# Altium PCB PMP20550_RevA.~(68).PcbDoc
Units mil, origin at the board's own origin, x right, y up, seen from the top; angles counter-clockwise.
Board outline 1966.66 x 1968.77 mil, 4 copper layers (Top Layer, POWER, GNDS, Bottom Layer), stack 79.834 mil thick; 56 components, 23 nets, 129 pads, 56 vias.
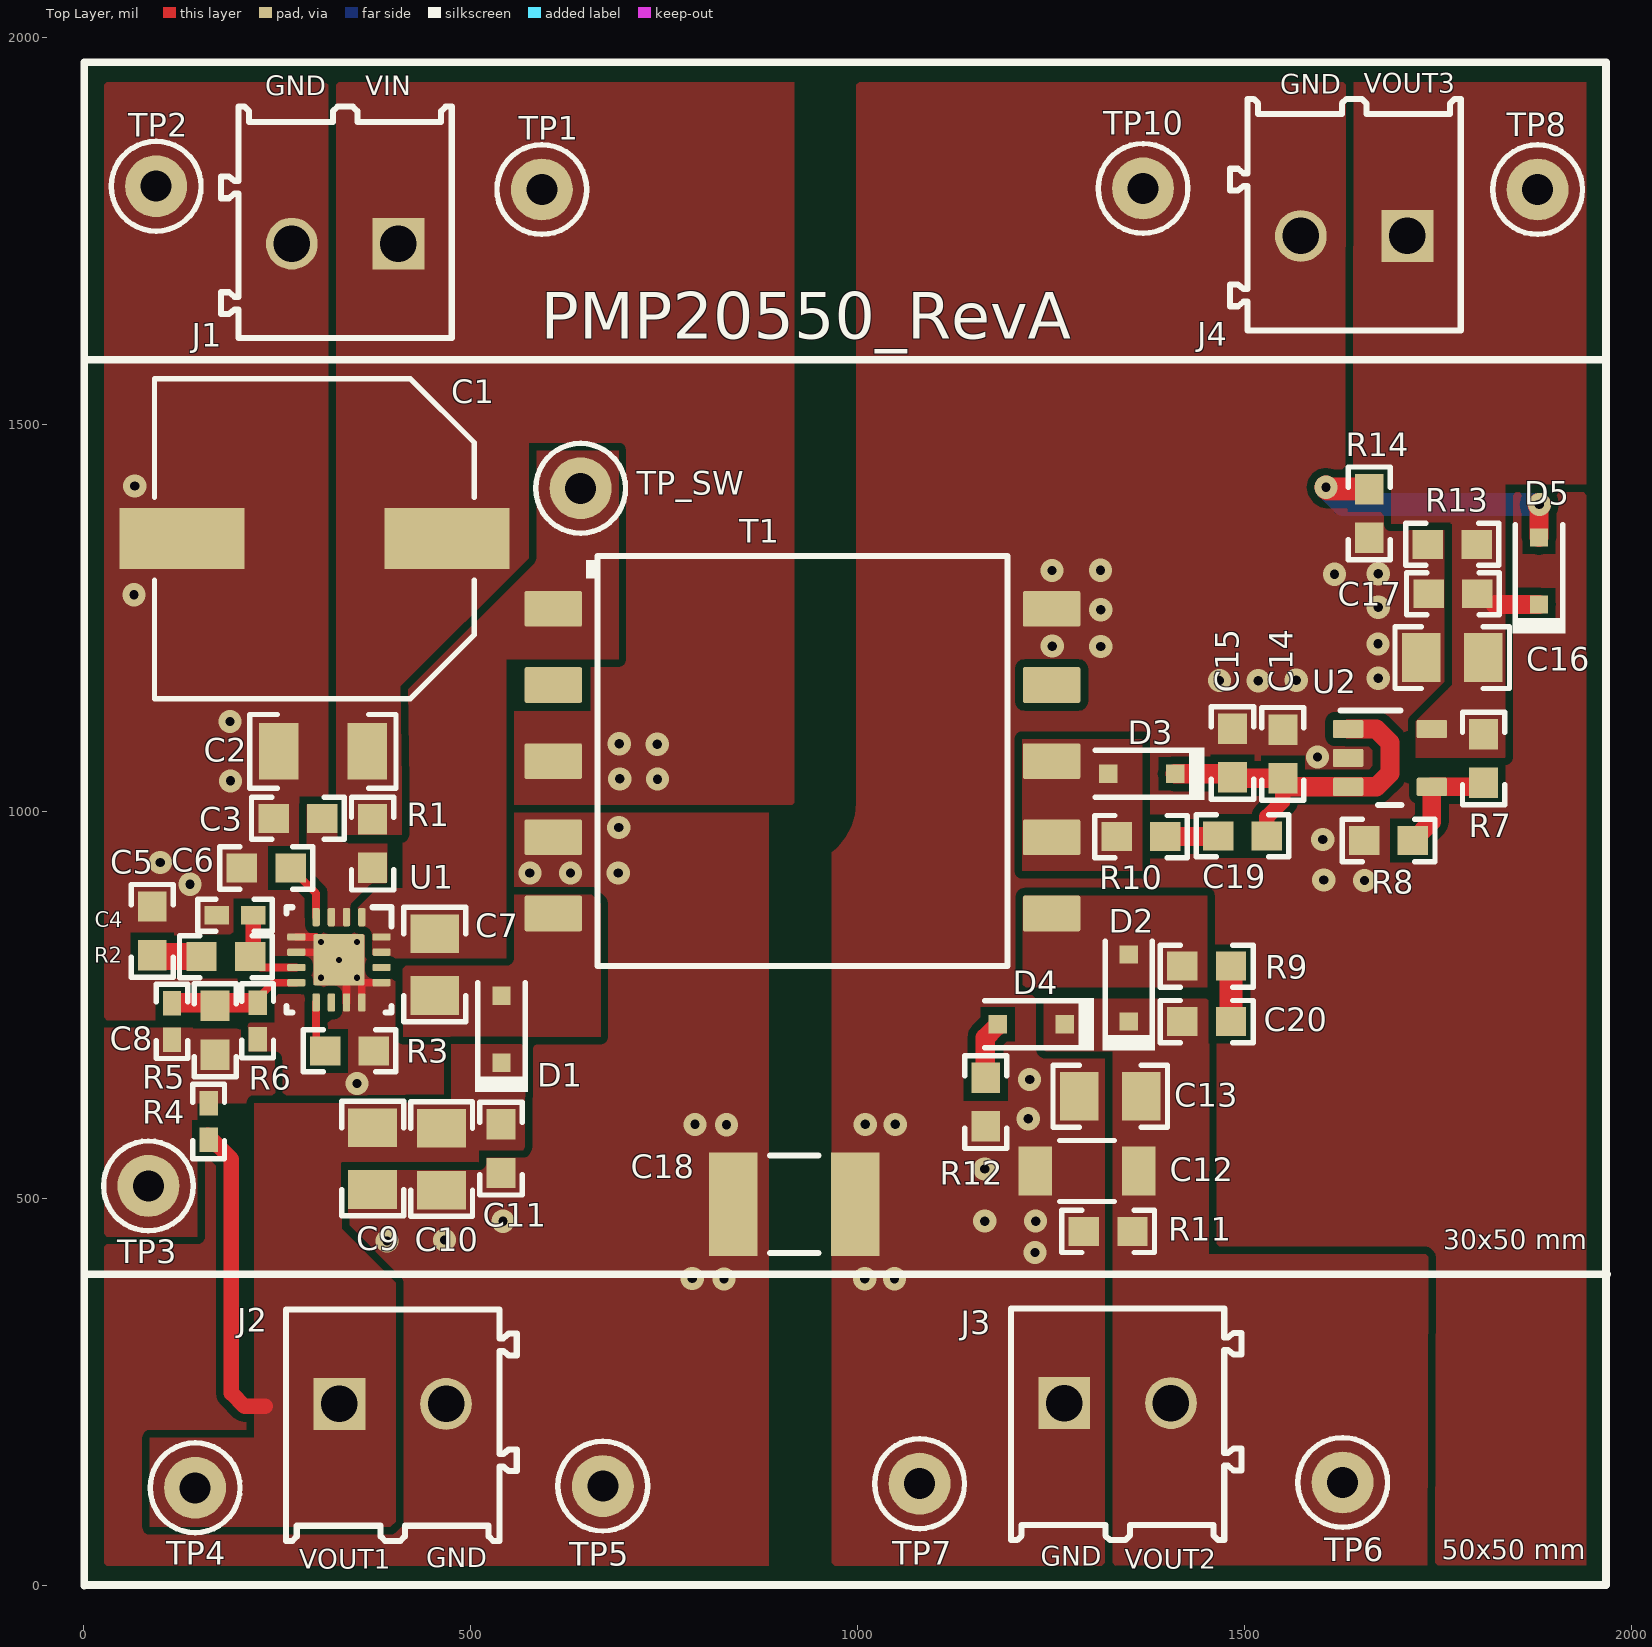
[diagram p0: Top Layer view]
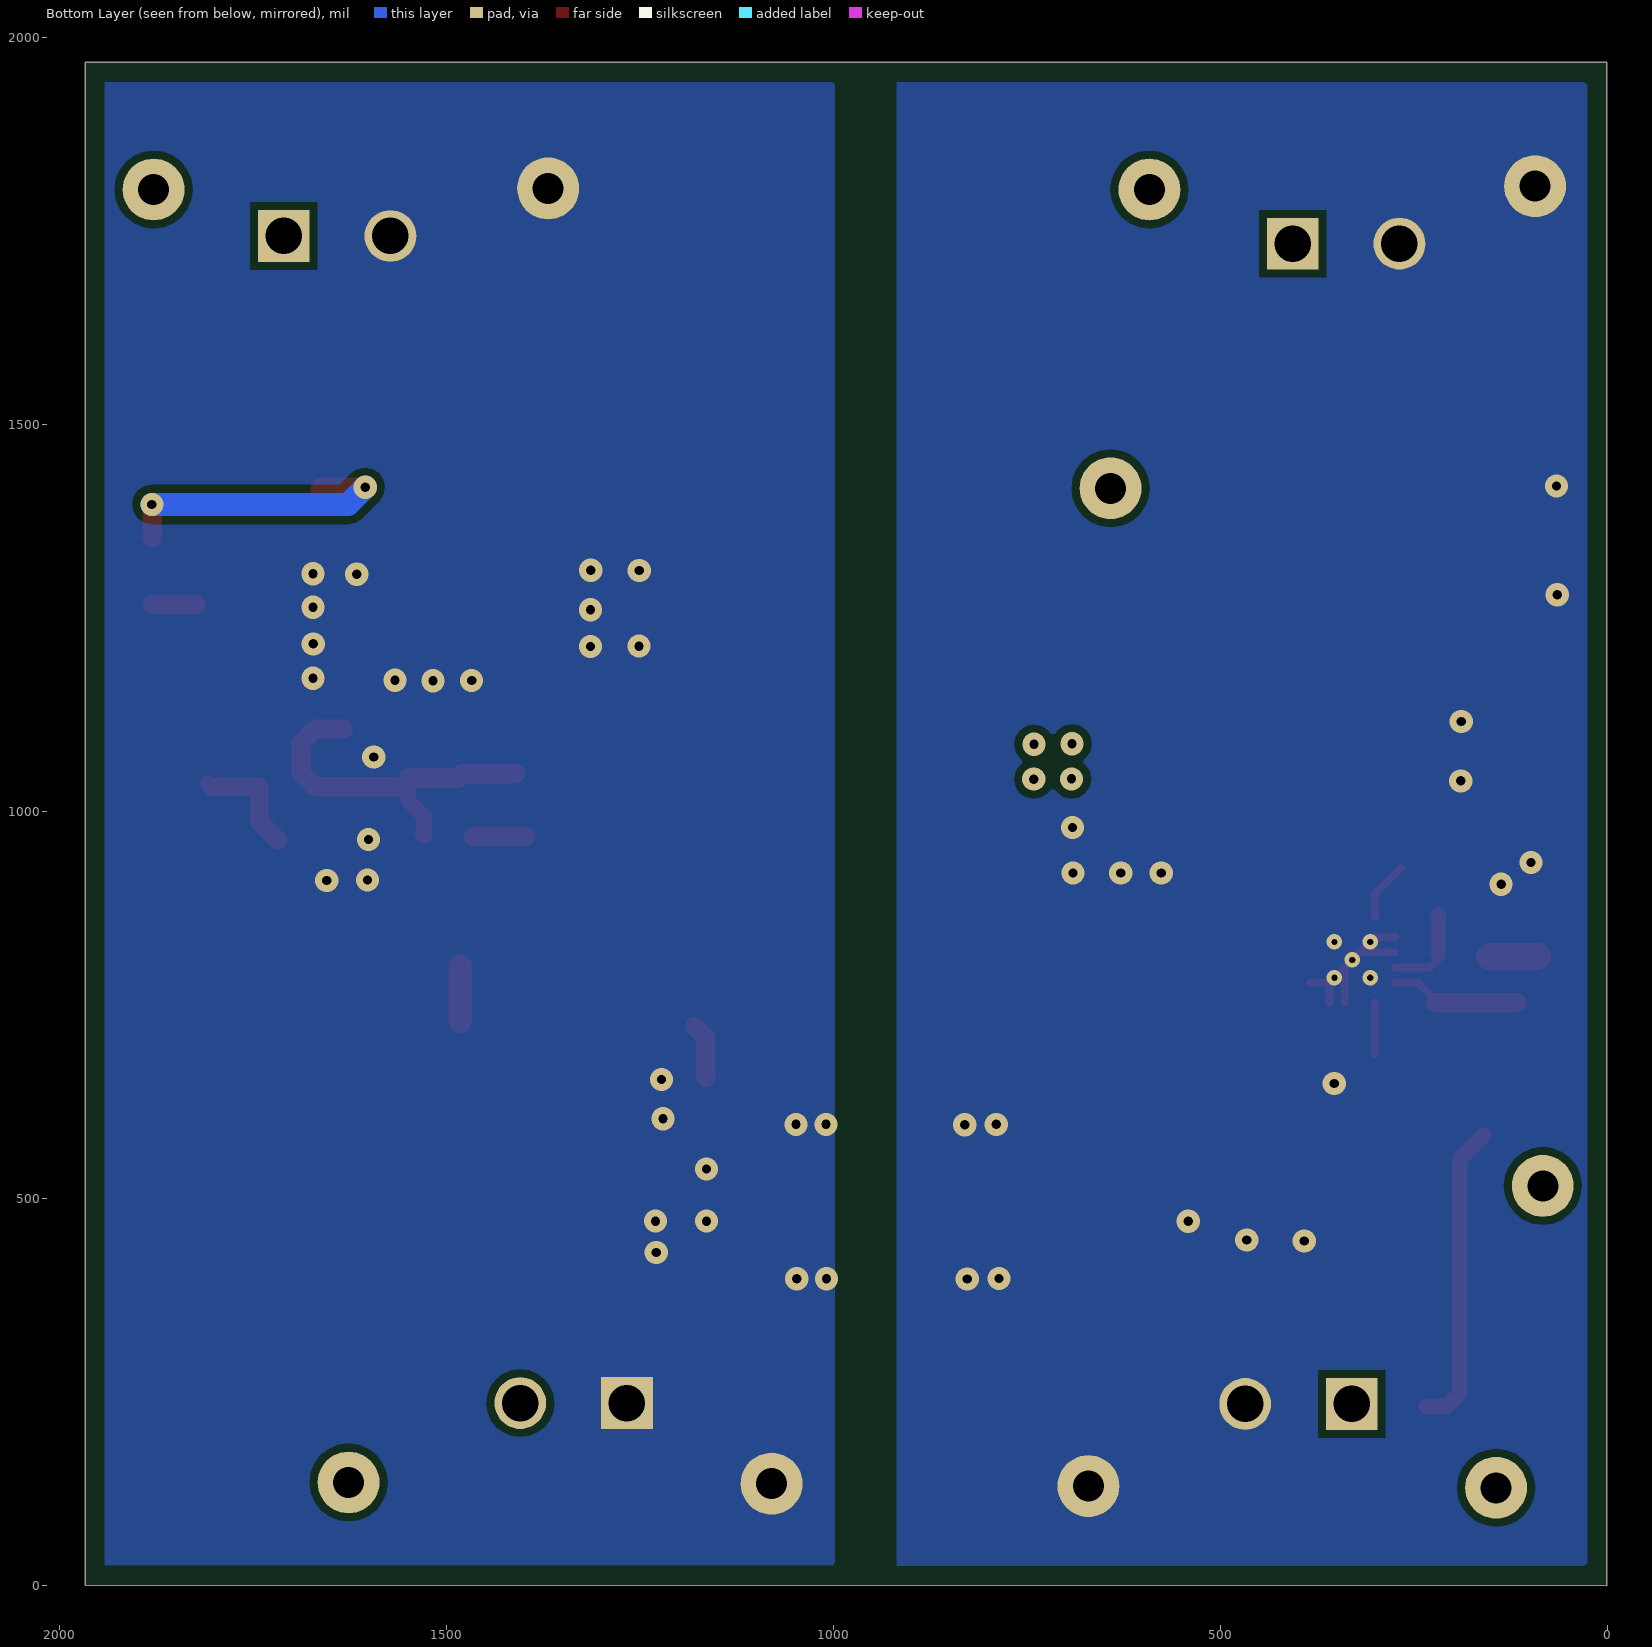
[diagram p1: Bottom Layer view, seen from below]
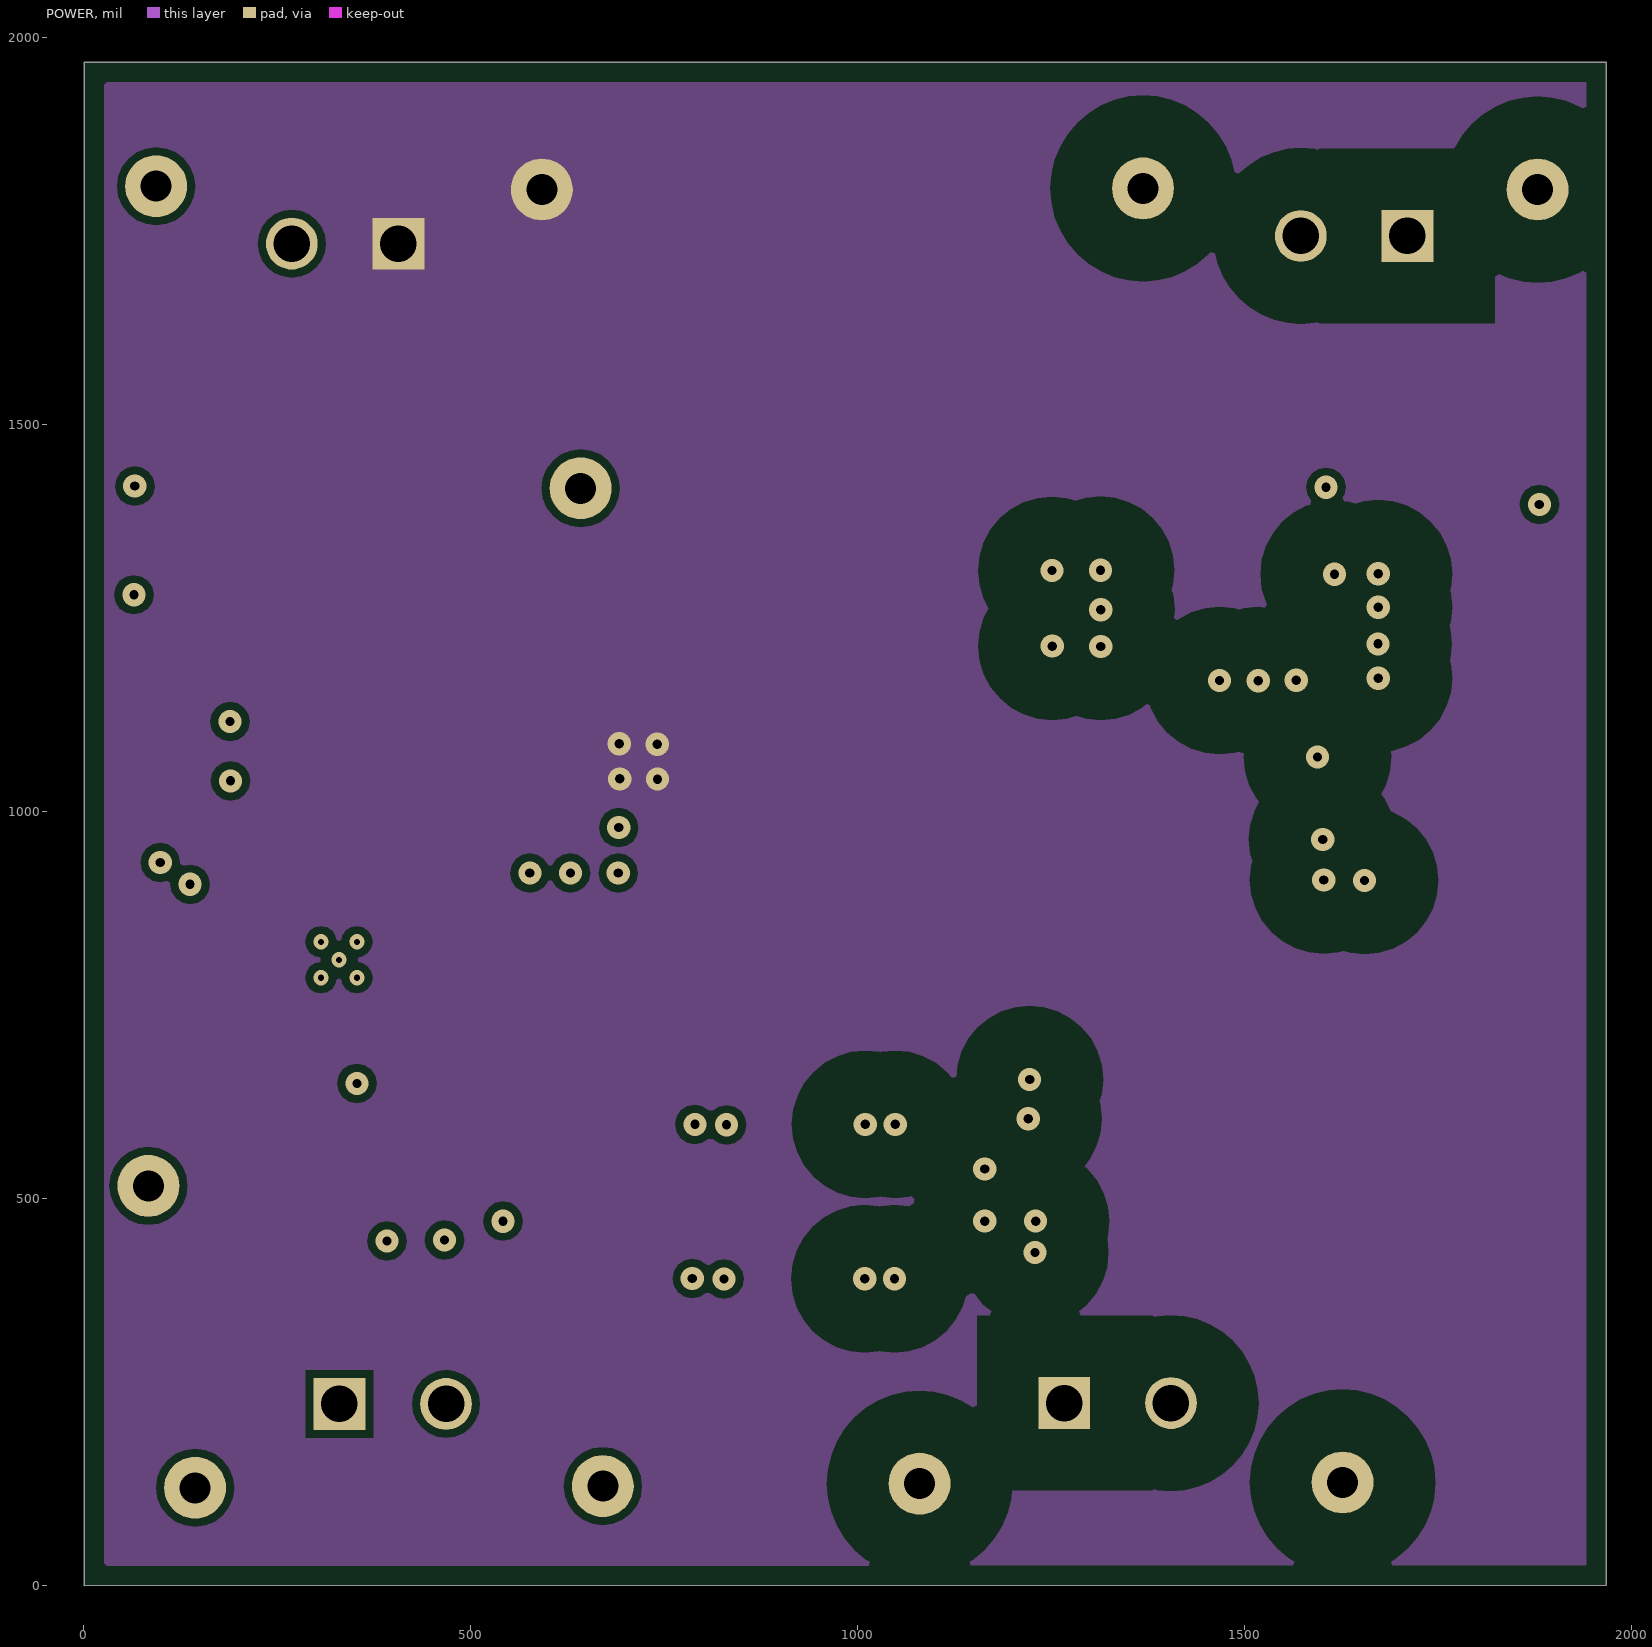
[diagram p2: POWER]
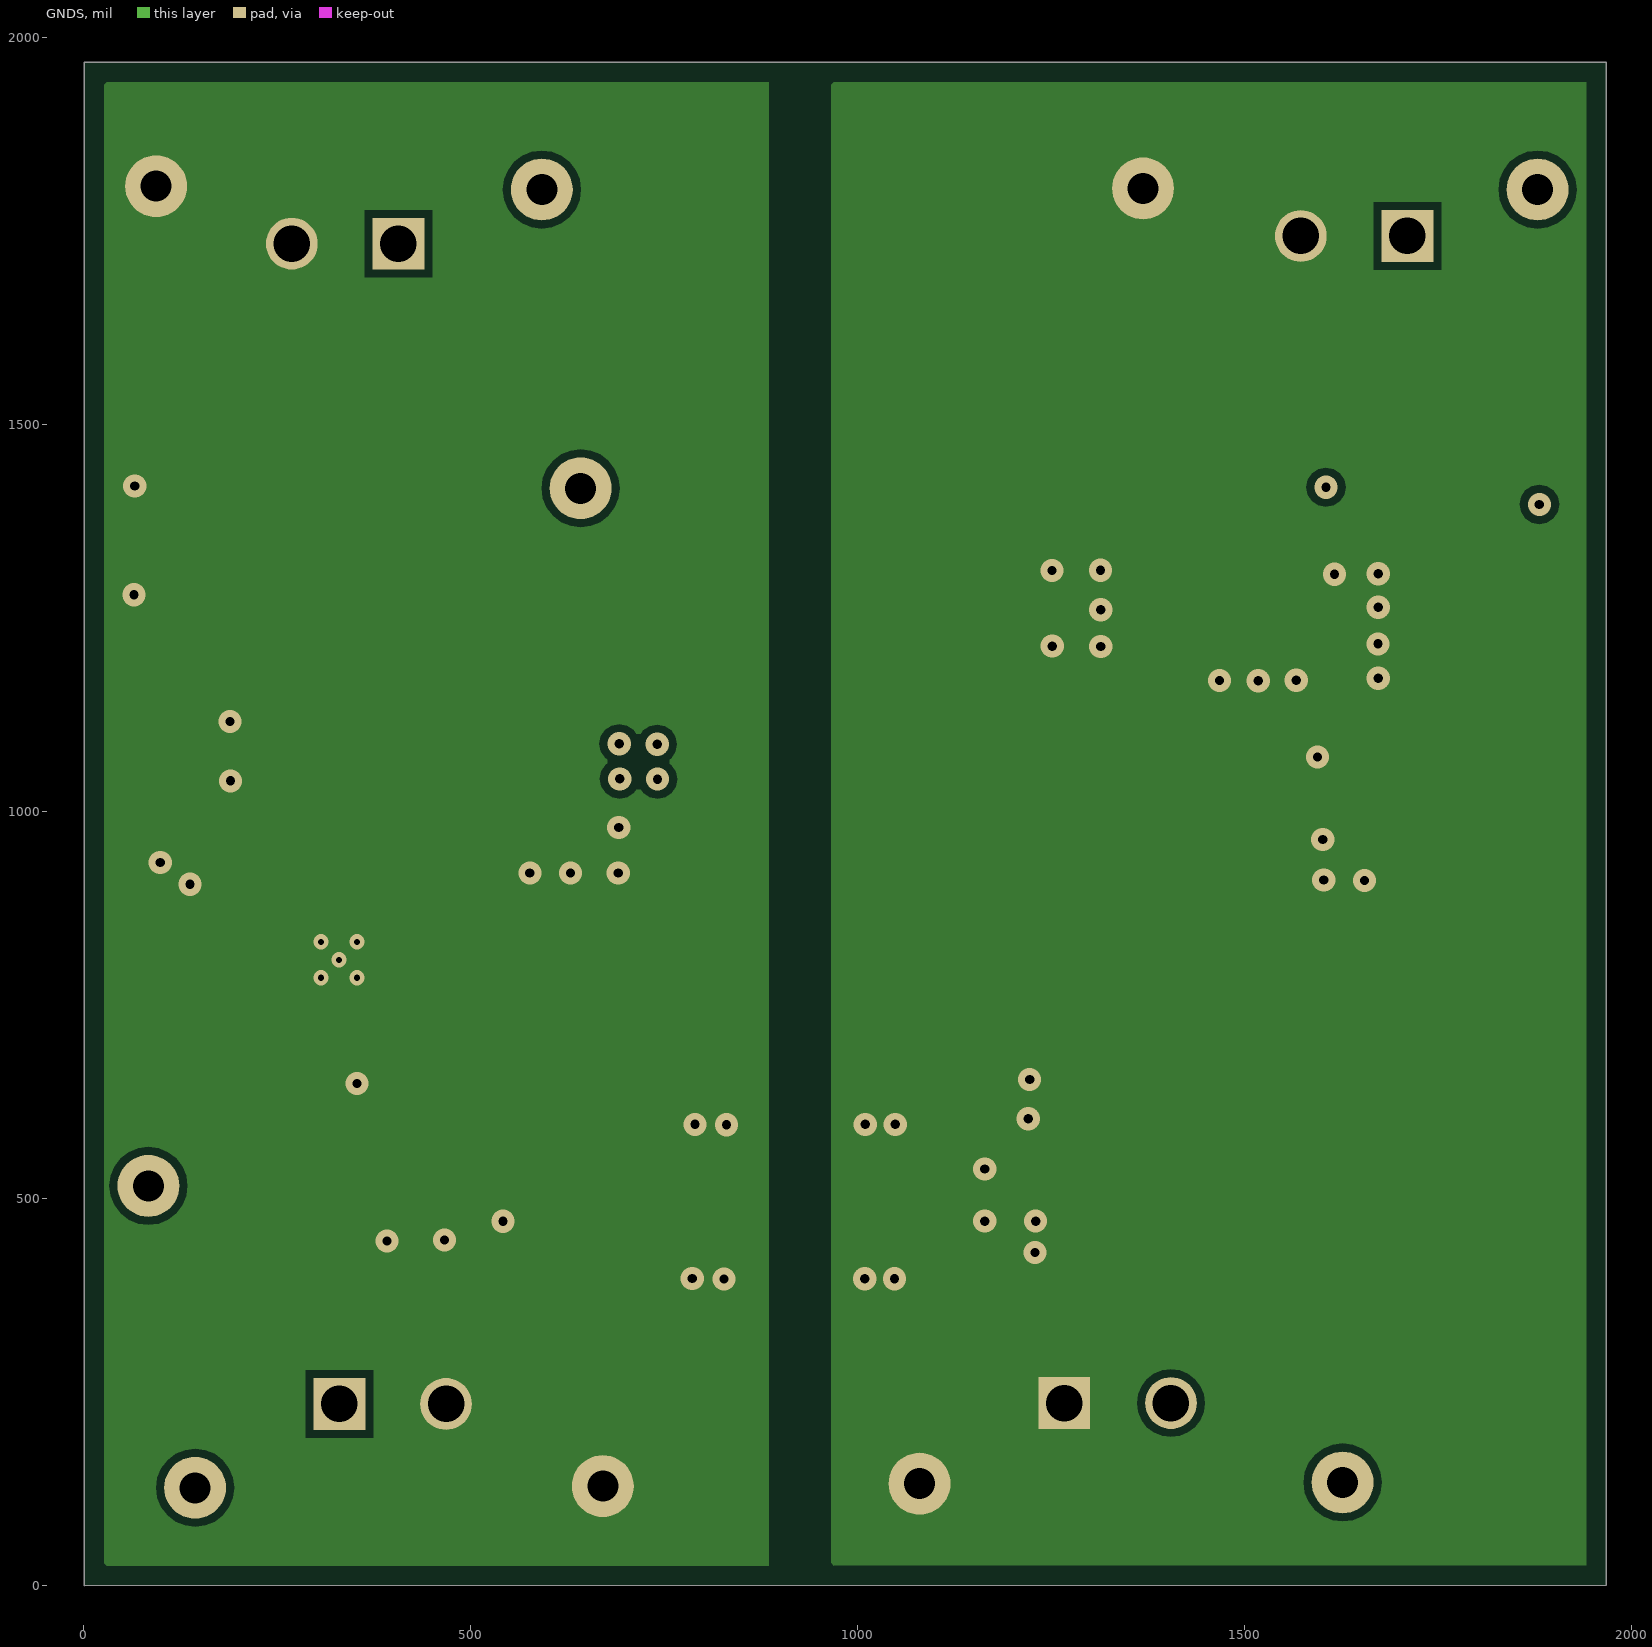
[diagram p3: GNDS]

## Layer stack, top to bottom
Top Solder: solder mask 0.4, Solder Resist, Dk 3.5
Top Layer: signal copper 1.4
Dielectric1: core 59.2, FR-4, Dk 4.8
POWER: signal copper 1.417
Dielectric 3: prepreg 5, Dk 4.2
GNDS: signal copper 1.417
Dielectric 2: core 10, Dk 4.2
Bottom Layer: signal copper 1.4
Bottom Solder: solder mask 0.4, Solder Resist, Dk 3.5

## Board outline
0.76,-0.43 0.76,1968.34 0.81,1968.29 1967.33,1968.29 1967.42,1968.2 1967.42,0.32 1967.36,0.38

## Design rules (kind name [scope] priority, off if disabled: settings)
AcuteAngle [All] p1: minimum=4.50000000000000E+0001 checktracksonly=FALSE
AssemblyTestPointUsage [All] p1: valid=2
BoardOutlineClearance BoardOutlineClearance_MountingHoles [OnCopper and InComponentClass('Mounting Holes')] p1: gap=40
BoardOutlineClearance BoardOutlineClearance_Poly [OnCopper and IsPoly] p2: gap=25
BoardOutlineClearance [OnCopper and Not InComponentClass('Logo') and not InComponentClass('FiducialMark') and not InRegion(1000,500,4000,800) and not InPoly] p3: gap=40
Clearance Clearance_2 [InNet('NetC1_1') vs InNetClass('Undefined')] p1: gap=80
Clearance Clearance_1 [InNet('GND') vs InNet('GND2')] p2: gap=80
Clearance Clearance_Keepouts [((IsTrack Or IsArc) And Not InPoly) And IsFree and IsKeepOut vs ((IsTrack Or IsArc) And Not InPoly) And IsFree and IsKeepOut] p3: gap=0
Clearance Clearance_Poly [InPolygon] p4: gap=10
Clearance [All] p5: gap=5
ComponentClearance ComponentClearance_MountingHoles_FiducialMarks [InComponentClass('Mounting Holes') vs InComponentClass('FiducialMark')] p1: gap=50 collisioncheckmode=3 verticalgap=10 showdistances=FALSE
ComponentClearance ComponentClearance_Shunt [InComponentClass('Header') vs InComponentClass('Shunt')] p2: gap=0 collisioncheckmode=3 verticalgap=0 showdistances=FALSE
ComponentClearance ComponentClearance_Logo [InComponentClass('Logo')] p3: gap=50 collisioncheckmode=3 verticalgap=10 showdistances=FALSE
ComponentClearance ComponentClearance_ScrewToNut [(HasFootprint('NY PMS 440 0025 PH')) vs (HasFootprint('Keystone_1902C'))] p4: gap=5 collisioncheckmode=3 verticalgap=10 showdistances=FALSE
ComponentClearance ComponentClearance_MountingHoles [InComponentClass('Mounting Holes')] p5: gap=250 collisioncheckmode=3 verticalgap=100000 showdistances=FALSE
ComponentClearance ComponentClearance_SmallPassives [HasFootprint('0201*') or HasFootprint('0402*') or HasFootprint('0508') or HasFootprint('0603*') or HasFootprint('0612') or HasFootprint('0805*') or HasFootprint('0815*') or HasFootprint('0830*') or HasFootprint('1206*') or HasFootprint('1210*') or HasFootprint('1808*') or HasFootprint('1812*') or HasFootprint('1825*') or HasFootprint('2010*') or HasFootprint('2220*') or HasFootprint('2225*') or HasFootprint('2512*') or HasFootprint('2728*') or HasFootprint('3518*') vs HasFootprint('0201*') or HasFootprint('0402*') or HasFootprint('0508') or HasFootprint('0603*') or HasFootprint('0612') or HasFootprint('0805*') or HasFootprint('0815*') or HasFootprint('0830*') or HasFootprint('1206*') or HasFootprint('1210*') or HasFootprint('1808*') or HasFootprint('1812*') or HasFootprint('1825*') or HasFootprint('2010*') or HasFootprint('2220*') or HasFootprint('2225*') or HasFootprint('2512*') or HasFootprint('2728*') or HasFootprint('3518*')] p6: gap=14.96 collisioncheckmode=3 verticalgap=10 showdistances=FALSE
ComponentClearance ComponentClearance_THtoSMT [IsThruComponent vs IsSMTComponent] p7: gap=40 collisioncheckmode=3 verticalgap=30 showdistances=FALSE
ComponentClearance ComponentClearance_THtoTH [IsThruComponent vs IsThruComponent] p8: gap=30 collisioncheckmode=3 verticalgap=30 showdistances=FALSE
ComponentClearance [All] p9: gap=30 collisioncheckmode=3 verticalgap=10 showdistances=FALSE
DiffPairsRouting [All] p1: maxlimit=100 minlimit=10 mostfreqgap=10 toplayer_minwidth=15 toplayer_maxwidth=15 toplayer_prefwidth=15 midlayer1_minwidth=15 midlayer1_maxwidth=15 midlayer1_prefwidth=15 midlayer2_minwidth=15 midlayer2_maxwidth=15 midlayer2_prefwidth=15 bottomlayer_minwidth=15 bottomlayer_maxwidth=15 bottomlayer_prefwidth=15 maxuncoupledlength=1000
FabricationTestPointUsage TestPointUsage [All] p1: valid=2 allowmultiple=FALSE
FabricationTestpoint Testpoint [All] p1: side=3 testpointundercomponent=TRUE minsize=40 maxsize=100 preferedsize=60 minholesize=0 maxholesize=40 preferedholesize=32 testpointgrid=1 allowsidetop=TRUE allowsidebottom=TRUE usegrid=TRUE gridtolerance=0.01
FanoutControl Fanout_LCC [IsLCC] p1: bgadir=Out bgaviamode=Centered fanoutstyle=Auto fanoutdirection=Alternating viagrid=1 // Fanout_LCC (Default Rule)
FanoutControl Fanout_BGA [IsBGA] p2: bgadir=Out bgaviamode=Centered fanoutstyle=Auto fanoutdirection=Alternating viagrid=1 // Fanout_BGA (Default Rule)
FanoutControl Fanout_Default [All] p4: bgadir=Out bgaviamode=Centered fanoutstyle=Auto fanoutdirection=Alternating viagrid=1 // Fanout_Default (Default Rule)
FanoutControl Fanout_Small [(CompPinCount < 5)] p5: bgadir=Out bgaviamode=Centered fanoutstyle=Auto fanoutdirection=OutThenIn viagrid=1 // Fanout_Small (Default Rule)
HoleSize [All] p1: absolutevalues=TRUE maxlimit=251 minlimit=7.87 maxpercent=80.000 minpercent=20.000
MinimumAnnularRing MinimumAnnularRing_ThermalPadVias [IsVia and InAnyComponent] p1: minimumring=5.91
MinimumAnnularRing [All] p2: minimumring=8
MinimumSolderMaskSliver MinimumSolderMaskSliver_Logo [InComponentClass('Logo') vs InComponentClass('Logo')] p1: minsoldermaskwidth=0.7
MinimumSolderMaskSliver [All] p2: minsoldermaskwidth=3.94
PlaneConnect [All] p1: planeconnectstyle=Direct reliefexpansion=10 reliefentries=4 reliefconductorwidth=10 reliefairgap=10
PolygonConnect [All] p1: connectstyle=Direct reliefconductorwidth=10 reliefentries=4 polygonreliefangle="90 Angle" airgapwidth=10
RoutingVias ThermalPadVias [IsVia and InAnyComponent] p1: holewidth=7.87 width=19.68 viastyle="Through Hole" minholewidth=7.87 minwidth=19.68 maxholewidth=12.99 maxwidth=23.62
RoutingVias [All] p2: holewidth=16 width=34 viastyle="Through Hole" minholewidth=7.87 minwidth=26 maxholewidth=40 maxwidth=65
SilkToBoardRegionClearance [Not ((IsComment or IsDesignator) And (Hide <> 'False')) and not InRegion(1000,500,4000,800)] p1:
SilkToSilkClearance SilkToSilkClearance_Pb-FreeLogo [(HasFootprint('Pb-Free_Overlay_Medium') OR HasFootprint('Pb-Free_Overlay_Small')) vs (HasFootprint('Pb-Free_Overlay_Medium') OR HasFootprint('Pb-Free_Overlay_Small'))] p1: silktosilkclearance=0
SilkToSilkClearance [All] p2: silktosilkclearance=0
SilkToSolderMaskClearance SilkToComponentPadClearance [IsPad and InAnycomponent] p1: minsilkscreentomaskgap=5 clearancetoexposedcopper=TRUE
SilkToSolderMaskClearance "Silk to Solder Mask Opening" [All] p2: minsilkscreentomaskgap=1 clearancetoexposedcopper=FALSE
SolderMaskExpansion [All] p1: expansion=1.97
Width [All] p1: maxlimit=100 minlimit=6 preferedwidth=10 checkconnectedcopper=TRUE
15 further rules are at their usual default settings.

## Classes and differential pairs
net class Undefined: GND2 NetC12_1 NetC14_1 NetC16_1 NetC19_2 NetC20_2 NetD2_2 NetD3_2 NetD4_2 NetR7_1

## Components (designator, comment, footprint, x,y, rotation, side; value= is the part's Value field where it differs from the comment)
C1 "EEE-FC1V221P" SM_RADIAL_G 298.19,1352.68 r180 top
C2 "GMK316AB7106KL" 1206 309.07,1077.86 r180 top
C3 "C1608X7R1E104K080AA" 0603 276.82,991.28 r180 top
C4 "GRM155R71E333KA88D" 0402 195.36,866.08 r180 top
C5 "C1608X7R1E104K080AA" 0603 88.53,845.82 r90 top
C6 "C1608X7R1E104K080AA" 0603 235.86,927.14 r180 top
C7 "LMK212B7105KG-T" 0805_HV 453.55,802.31 r90 top
C8 "GRM1555C1H201JA01D" 0402 114.02,728.86 r90 top
C9 "GRM21BZ71A226ME15L" 0805_HV 373.34,551.49 r270 top
C10 "GRM21BZ71A226ME15L" 0805_HV 462.39,550.81 r270 top
C11 "C0603X104K8RACTU" 0603 539.2,564.41 r270 top
C12 "C3216X5R1E336M160AC" 1206_180 1296.37,535.6 r180 top
C13 "08053C104KAT2A" 0805_HV 1326.68,632.19 r180 top
C14 "GRM188Z71A106MA73D" 0603 1549.68,1074.57 r90 top
C15 "C1608X7R1E104K080AA" 0603 1484.7,1075.67 r90 top
C16 "C2012X7R1E474K125AA" 0805_HV 1768.67,1199.08 r180 top
C17 "C0603X104K8RACTU" 0603 1769.56,1281.56 r180 top
C18 "GR443QR73D102KW01L" 1812 918.24,492.28 r180 top
C19 "GRM1885C1H111JA01D" 0603 1497.61,968.66 r180 top
C20 "GRM1885C1H111JA01D" 0603 1451.23,728.57 r0 top
D1 "PMEG2020EJ,115" SOD-323F 539.88,718.71 r90 top
D2 "PMEG2020EJ,115" SOD-323F 1350.47,772.12 r90 top
D3 "PMEG2020EJ,115" SOD-323F 1367.26,1048.84 r180 top
D4 "MMSZ5235BS-7-F" SOD-323 1224.44,725.13 r180 top
D5 "MMSZ5235BS-7-F" SOD-323 1880.72,1310.98 r90 top
J1 "1984617" Phoenix_1984617 337.81,1733.95 r180 top
J2 "1984617" Phoenix_1984617 399.35,234.48 r0 top
J3 "1984617" Phoenix_1984617 1336.21,235.56 r0 top
J4 "1984617" Phoenix_1984617 1641.85,1743.96 r180 top
R1 "ERJ-3GEY0R00V" 0603 373.34,958.65 r90 top
R2 "RC0603FR-073K01L" 0603 183.69,812.51 r0 top
R3 "CRCW0603162KFKEA" 0603 343.43,690.84 r180 top
R4 "ERJ-2RKF49R9X" 0402 161.46,599.43 r270 top
R5 "CRCW060330K9FKEA" 0603 169.79,717.32 r270 top
R6 "ERJ-2RKF1002X" 0402 224.73,729.51 r90 top
R7 "RC0603FR-0778K7L" 0603 1809.17,1068.6 r90 top
R8 "CRCW060324K9FKEA" 0603 1686.34,962.61 r0 top
R9 "CPF0603B1K62E" 0603 1451.23,800.16 r180 top
R10 "CPF0603B1K62E" 0603 1366.36,967.77 r180 top
R11 "CPF0603B1K62E" 0603 1323.9,457.41 r180 top
R12 "CPF0603B1K62E" 0603 1165.73,624.55 r270 top
R13 "CPF0603B1K62E" 0603 1768.67,1345.41 r180 top
R14 "CPF0603B1K62E" 0603 1661.36,1385.32 r270 top
T1 "750316553" Wurth_750316553 928.88,1065.16 r0 top
TP1 "5000" Keystone5000 592.04,1803.94 r90 top
TP2 "5001" Keystone5001 93.57,1808.22 r90 top
TP3 "5003" Keystone5003 83.6,516.27 r0 top
TP4 "VBUS" Keystone5000 143.95,126.09 r90 top
TP5 "5001" Keystone5001 670.84,128.24 r90 top
TP6 "5000" Keystone5000 1627,132.97 r0 top
TP7 "5001" Keystone5001 1080.24,131.4 r0 top
TP8 "5000" Keystone5000 1878.95,1803.95 r0 top
TP10 "5001" Keystone5001 1369.04,1805.37 r90 top
TP_SW "5001" Keystone5001 642.2,1417.84 r90 top
U1 "TPS55340QRTERQ1" RTE0016C 329.84,808.43 r270 top
U2 "TPS73201QDBVRQ1" DBV0005A_N 1688.2,1069.39 r0 top

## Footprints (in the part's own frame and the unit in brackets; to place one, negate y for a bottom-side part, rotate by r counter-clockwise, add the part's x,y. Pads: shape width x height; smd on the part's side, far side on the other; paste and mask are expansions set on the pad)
0402 [mm] "0402 from SM-752 data"
  rect 0.8x0.6 smd: 1(-0.6,0) 2(0.6,0)
  silkscreen extent -1.22,-0.52 1.22,0.52, body extent -0.55,-0.3 0.55,0.3, height 0.6
0603 [mm] "0603 from SM-752 data"
  rect 1x0.95 smd: 1(-0.8,0) 2(0.8,0)
  silkscreen extent -1.52,-0.69 1.52,0.69, body extent -0.87,-0.47 0.87,0.47, height 1
0805_HV [mil] "0805 with 30mil clearance between pads"
  rect 50x63 smd: 1(-40,0) 2(40,0)
  silkscreen extent -74,-40 74,40, body extent -43,-29 43,29, height 57
1206 [mm] "1206 from SM-752 data"
  rect 1.3x1.85 smd: 1(-1.45,0) 2(1.45,0)
  silkscreen extent -2.4,-1.21 2.4,1.21, body extent -1.7,-0.9 1.7,0.9, height 1.35
1206_180 [mm] "1206_180"
  rect 1.1x1.6 smd: 1(-1.7,0) 2(1.7,0)
  silkscreen extent -0.9,-1 0.9,1, body extent -1.75,-0.95 1.75,0.95, height 1.8
1812 [mm]
  rect 1.6x3.4 smd: 1(-2,0) 2(2,0)
  silkscreen extent -0.8,-1.6 0.8,1.6, body extent -2.4,-1.7 2.4,1.7, height 1.35
DBV0005A_N [mm] "SOT23, 5-Leads, Body 2.9x1.6mm, Pitch 0.95mm, Lead Span 2.8mm, IPC Medium Density"
  rrect17% 1x0.6 smd: 1(-1.375,0.95) 2(-1.375,0) 3(-1.375,-0.95) 4(1.375,-0.95) 5(1.375,0.95)
  silkscreen extent -1.63,-1.55 0.38,1.55, body extent -1.42,-1.46 1.42,1.46, height 1.09
Keystone5000 [mil] "For Keystone 500x miniature loop terminals"
  round 80 hole 40: 1(0,0)
  silkscreen extent -58,-58 58,58, body extent -49,-49 49,49, height 182
Keystone5001 [mil] "For Keystone 500x miniature loop terminals"
  round 80 hole 40: 1(0,0)
  silkscreen extent -58,-58 58,58, body extent -49,-49 49,49, height 182
Keystone5003 [mil] "For Keystone 500x miniature loop terminals"
  round 80 hole 40: 1(0,0)
  silkscreen extent -58,-58 58,58, body extent -49,-49 49,49, height 182
Phoenix_1984617 [mm] "Terminal Block, 3.5mm, 2x1, TH"
  rect 1.7x1.7 hole 1.2: 1(-1.75,0)
  round 1.7 hole 1.2: 2(1.75,0)
  silkscreen extent -3.5,-4.5 4.07,3.1, body extent -3.5,-4.5 4.07,3.1, height 9
RTE0016C [mm] "Texas Insturments"
  rrect42% 0.6x0.24 smd: 1(-1.4,0.75) 2(-1.4,0.25) 3(-1.4,-0.25) 4(-1.4,-0.75) 9(1.4,-0.75) 10(1.4,-0.25) 11(1.4,0.25) 12(1.4,0.75)
  rrect42% 0.24x0.6 smd: 5(-0.75,-1.4) 6(-0.25,-1.4) 7(0.25,-1.4) 8(0.75,-1.4) 13(0.75,1.4) 14(0.25,1.4) 15(-0.25,1.4) 16(-0.75,1.4)
  rrect6% 1.55x1.55 on Top Paste: 17(0,0)
  rrect6% 1.68x1.68 smd paste-0.85: 17(0,0)
  silkscreen extent -1.72,-1.73 1.72,1.73, body extent -1.57,-1.57 1.58,1.58, height 0.81
SM_RADIAL_G [mm] "10 x 10.2mm:  Panasonic G"
  rect 4.1x2 smd: 1(-4.35,0) 2(4.35,0)
  silkscreen extent -5.25,-5.25 5.25,5.25, body extent -5.25,-5.25 5.25,5.25, height 10.5
SOD-323 [mm] "NXP recommended land pattern"
  rect 0.6x0.6 smd paste-0.05: 1(-1.1,0) 2(1.1,0)
  silkscreen extent -2.06,-0.86 1.53,0.86, body extent -1.3,-0.67 1.3,0.68, height 1.1
SOD-323F [mm] "NXP recommended land pattern"
  rect 0.6x0.6 smd paste-0.05: 1(-1.1,0) 2(1.1,0)
  silkscreen extent -2.06,-0.86 1.53,0.86, body extent -1.35,-0.67 1.35,0.68, height 0.79
Wurth_750316553 [mm] "SMD, 10-Leads, Body 17.75x13.46mm, Pitch 2.5mm"
  rrect9% 1.88x1.17 smd: 1(-8.18,5) 2(-8.18,2.5) 3(-8.18,0) 4(-8.18,-2.5) 5(-8.18,-5) 6(8.18,-5) 7(8.18,-2.5) 8(8.18,0) 9(8.18,2.5) 10(8.18,5)
  silkscreen extent -7.1,-6.73 6.73,6.73, body extent -8.87,-6.73 8.88,6.73, height 12.7

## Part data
C1: "CAP, AL, 220 µF, 35 V, +/- 20%, 0.15 ohm, SMD"
C2: "CAP, CERM, 10 µF, 35 V, +/- 10%, X7R, 1206"
C3 C5 C6 C15: "CAP, CERM, 0.1 µF, 25 V, +/- 10%, X7R, 0603"
C4: "OPEN, 0402"
C7: "CAP, CERM, 1 µF, 10 V, +/- 10%, X7R, 0805"
C8: "CAP, CERM, 200 pF, 50 V, +/- 5%, C0G/NP0, 0402"
C9 C10: "CAP, CERM, 22 µF, 10 V, +/- 20%, X7R, 0805"
C11 C17: "CAP, CERM, 0.1 µF, 10 V, +/- 10%, X7R, 0603"
C12: "CAP, CERM, 33 µF, 25 V, +/- 20%, X5R, 1206"
C13: "CAP, CERM, 0.1 µF, 25 V, +/- 10%, X7R, 0805"
C14: "CAP, CERM, 10 µF, 10 V, +/- 20%, X7R, 0603"
C16: "CAP, CERM, 4.7 µF, 25 V, +/- 10%, X7R, 0805"
C18: "CAP, CERM, 1000 pF, 2000 V, +/- 10%, X7R, 1812"
C19 C20: "CAP, CERM, 110 pF, 50 V, +/- 5%, C0G/NP0, 0603"
D1 D2 D3: "Diode, Schottky, 20 V, 2 A, SOD-323F"
D4 D5: "Diode, Zener, 6.8 V, 200 mW, SOD-323"
J1 J2 J3 J4: "Terminal Block, 3.5mm, 2x1, TH"
R1: "RES, 0, 5%, 0.1 W, 0603"
R2: "RES, 3.01 k, 1%, 0.1 W, 0603"
R3: "RES, 162 k, 1%, 0.1 W, 0603"
R4: "RES, 49.9, 1%, 0.1 W, AEC-Q200 Grade 0, 0402"
R5: "RES, 30.9 k, 1%, 0.1 W, 0603"
R6: "RES, 10.0 k, 1%, 0.1 W, 0402"
R7: "RES, 78.7 k, 1%, 0.1 W, 0603"
R8: "RES, 24.9 k, 1%, 0.1 W, 0603"
R9 R10 R11 R12 R13 R14: "RES, 1.62 k, 0.1%, 0.063 W, 0603"
T1: "Transformer, 52 uH, SMT"
TP1 TP6 TP8: "Test Point, Miniature, Red, TH"
TP2 TP5 TP7 TP10 TP_SW: "Test Point, Miniature, Black, TH"
TP3: "Test Point, Miniature, Orange, TH"
TP4: library part 5000, "Test Point, TH, Miniature, Red"
U1: "Integrated 5-A 40-V Wide Input Range Boost/SEPIC/Flyback DC-DC Regulator, RTE0016C"
U2: "Single Output Fast Transient Response LDO, 250 mA, Adjustable 1.2 to 5.5 V Output, 1.7 to 5.5 V Input, 5-pin SOT-23 (DBV), -40 to 125 degC, Green (RoHS & no Sb/Br)"

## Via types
v1: diameter 30, hole 12, Top Layer to Bottom Layer, 28 vias
v2: diameter 30, hole 12, Top Layer to Bottom Layer, tented top, 21 vias
v3: diameter 19.68, hole 7.87, Top Layer to Bottom Layer, tented top, 5 vias
v4: diameter 30, hole 12, Top Layer to Bottom Layer, tented both sides, 2 vias

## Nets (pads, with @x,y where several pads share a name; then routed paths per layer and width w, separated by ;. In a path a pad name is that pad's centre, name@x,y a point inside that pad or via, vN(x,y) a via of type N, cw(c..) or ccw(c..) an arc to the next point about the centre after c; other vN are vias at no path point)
GND: C1.2 C2.2 C3.2 C4.2 C5.2 C6.2 C9.2 C10.2 C11.2 C18.2 J1.2 J2.2 R3.1 R6.1 T1.4 TP2.1 TP5.1 U1.5 U1.6 U1.11 U1.12 U1.13 U1.17@329.84,808.43 | length 241.9
  Top Layer w10: U1.6 U1.17@320,818.27 ; U1.5 U1.17@300.31,837.96 ; v3(306.61,831.66) U1.17@320,818.27 ; U1.11 U1.17@339.68,798.59 ; U1.12 U1.17@359.37,778.9 ; U1.13 U1.17@359.37,778.9 ; U1.17@320,818.27 v3(329.84,808.43) U1.17@339.68,798.59 ; U1.17@339.68,798.59 U1.17@359.37,778.9
  other v1: 827.36,395.96 786.45,396.54 830.79,595.16 789.88,595.74 576.59,920.49 628.98,920.57 690.83,920.57 691.46,979.3 64.86,1280.25 66.03,1420.67
  other v2: 391.88,444.99 466.19,446.31 541.83,470.64 353.02,648.7 137.45,905.98 98.86,934.25 189.63,1039.7 189.09,1116.34
  other v3: 306.61,785.2 353.07,785.2 353.07,831.66
GND2: C12.2 C13.2 C14.2 C15.2 C16.2 C17.2 C18.1 J3.1 J4.2 R8.1 R11.2 R12.2 R13.2 R14.2 T1.10 TP7.1 TP10.1 U2.2
  other v1: 1009.28,396.19 1047.87,396.19 1229.51,430.19 1164.4,470.71 1230.23,470.71 1010.06,595.74 1048.66,595.74 1220.68,602.9 1222.48,653.72 1314.43,1213.48 1251.67,1213.82 1314.43,1260.8 1251.33,1311.56 1314.09,1311.9
  other v2: 1164.4,537.99 1655.26,911 1602.62,911.69 1601.3,964.03 1594.56,1070.62 1467.99,1169.37 1517.94,1169.03 1566.99,1169.77 1673,1172.4 1672.72,1216.75 1673,1264.17 1616.38,1306.85 1673,1307.4
NetC1_1: C1.1 C2.1 J1.1 R1.2 T1.3 TP1.1
  other v1: 692.69,1042.27 741.53,1041.95 741.2,1086.91 692.04,1087.56
NetC3_1: C3.1 R1.1 U1.2 U1.3
NetC4_1: C4.1 R2.2 U1.7 | length 120.4
  Top Layer w10: R2.2@218.99,816.3 R2.2 229.11,798.59 U1.7
  Top Layer w20: R2.2@218.99,816.3 C4.1
NetC5_1: C5.1 R2.1 | length 64.4
  Top Layer w20: C5.1 C5.1@90.34,812.51
  Top Layer w35: C5.1@90.34,812.51 R2.1
NetC6_1: C6.1 U1.4 | length 77.2
  Top Layer w10: C6.1 300.31,894.18 U1.4
NetC7_1: C7.1 D1.2 T1.5
NetC7_2: C7.2 T1.1 TP_SW.1 U1.1 U1.15 U1.16
NetC8_1: C8.1 R4.1 R5.2 TP3.1
NetC8_2: C8.2 R5.1 R6.2 U1.8 | length 181.8
  Top Layer w10: R6.2@216.32,750.2 245.03,778.9 U1.8
  Top Layer w20: 211.79,754.73 R6.2@216.32,750.2
  Top Layer w25: C8.2@117.32,753.03 R6.2@222.4,753.03
NetC9_1: C9.1 C10.1 C11.1 D1.1 J2.1 R4.2 TP4.1 | length 396.9
  Top Layer w20: R4.2@160.13,581.73 190.91,550.91 190.7,248.47 207.9,231.27 234.5,231.27
NetC12_1: C12.1 C13.1 C20.1 D2.1 D4.1 J3.2 R11.1 TP6.1
NetC14_1: C14.1 C15.1 C19.1 D3.1 U2.1 U2.3 | length 479.4
  Top Layer w20: C15.1@1480.03,1048.84 C15.1 C15.1@1485.8,1043.07 ; C19.1@1531.61,971.16 C19.1 1529.11,993.09 1549.68,1013.65 C14.1 C14.1@1560.76,1031.99
  Top Layer w25: D3.1 C15.1@1480.03,1048.84 ; C15.1@1485.8,1043.07 C14.1 ; C14.1@1560.76,1031.99 U2.3 1670.64,1031.99 1688.2,1049.55 1688.2,1089.07 1670.48,1106.79 U2.1
NetC16_1: C16.1 C17.1 D5.1 J4.1 R7.2 R13.1 TP8.1 U2.5 | length 58.7
  Top Layer w20: 1822.6,1268.99 1823.92,1267.68
  Top Layer w24: 1823.92,1267.68 D5.1
NetC19_2: C19.2 R10.1 | length 68.6
  Top Layer w20: C19.2@1465.23,967.77 C19.2
  Top Layer w25: R10.1 C19.2@1465.23,967.77
NetC20_2: C20.2 R9.1 | length 71.6
  Top Layer w30: C20.2 R9.1
NetD2_2: D2.2 R9.2 T1.6
NetD3_2: D3.2 R10.2 T1.7 T1.8
NetD4_2: D4.2 R12.1 | length 73.5
  Top Layer w20: R12.1@1165.22,656.55 R12.1 ; D4.2@1181.13,723.71 D4.2
  Top Layer w25: R12.1@1165.22,656.55 1165.22,707.8 D4.2@1179.33,722.07
NetD5_2: D5.2 R14.1 | length 384.9
  Top Layer w25: D5.2 v4@1880.72,1396.47
  Top Layer w30: v4(1605.46,1419.16) 1607.81,1416.82 R14.1 ; v4@1880.72,1396.47 v4(1881.24,1396.99)
  Bottom Layer w30: v4(1605.46,1419.16) 1627.55,1397.07 1627.72,1397.24 1627.97,1396.99 v4(1881.24,1396.99)
NetR3_2: R3.2 U1.9 | length 67.7
  Top Layer w10: U1.9 R3.2@300.46,685.63
NetR7_1: R7.1 R8.2 U2.4 | length 148.5
  Top Layer w20: R7.1@1804.05,1031.99 R7.1
  Top Layer w24: R8.2 1742.33,987.1 U2.4 R7.1@1804.05,1031.99
pads on no net: T1.2 T1.9 U1.10 U1.14 U1.17@329.84,808.43

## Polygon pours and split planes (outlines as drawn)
GND2 on Top Layer "top-gnd2" (solid, pour order 40): 1965.51,6.55 966.87,6.55 966.87,1956.5 1960.78,1956.5
GND on Top Layer "top-gnd1" (solid, pour order 38): 3.73,1.82 6.1,4.19 885.03,4.19 885.03,1963.6 3.73,1963.6
NetC1_1 on Top Layer "TOP - VIN" (solid, pour order 0): 326.69,1962.37 326.27,1961.95 326.27,969.98 348.8,969.98 364.8,969.98 380.58,969.98 397.22,969.98 410.93,969.98 410.93,1038.69 409.32,1161.98 575.05,1327.72 575.05,1476.9 681.05,1476.9 679.63,1612.97 680.81,1614.15 680.81,1961.19
NetC7_2 on Top Layer "TOP - SW" (solid, pour order 2): 366.1,810.66 534.94,810.66 546.12,810.66 546.12,821.84 546.12,1197.01 644.16,1197.01 651.13,1197.01 661.94,1197.01 691.2,1197.01 691.2,1320.83 691.2,1466.63 581.25,1466.63 581.25,1320.83 424.37,1163.94 412.25,1151.83 412.25,901.05 379.54,901.05 348.65,870.16
NetC1_1 on Top Layer "TOP  VIN2" (solid, pour order 4): 655.45,1129.45 574.13,1129.45 555.26,1129.45 555.26,1008.97 915.39,1008.97 916.49,1010.08 918.07,1011.65 918.07,1944.52 655.45,1942.77 680.81,1942.77 655.45,1532.27
NetC9_1 on Top Layer "VOUT1" (solid, pour order 6): 570.52,701.19 568.52,699.19 475.22,699.19 475.22,624.96 366.27,623.13 220.05,623.13 220.05,190.77 85.43,190.77 85.43,75.44 396.31,75.44 397.81,76.94 403.27,82.39 403.27,374.59 403.27,391.11 333.33,461.05 333.33,483.08 333.33,546.53 553.65,546.53 569.97,562.85
NetC12_1 on Top Layer "VOUT2" (solid, pour order 10): 1736.34,5.08 1331.62,5.08 1329.2,2.66 1329.69,3.15 1329.69,690.5 1243.04,690.5 1240.48,693.05 1240.48,758.42 1450.65,758.42 1451.07,758.01 1454.38,754.7 1454.38,696.36 1454.38,642.74 1454.38,642.17 1454.09,427.95 1737.7,427.95
NetC16_1 on Top Layer "VOUT3" (solid, pour order 12): 1641.28,1961.04 1958.77,1961.04 1958.77,1493.72 1958.77,1422.73 1837.27,1422.73 1837.27,1322.52 1837.27,1069.04 1837.71,1068.6 1836.42,1069.89 1721.33,1069.89 1721.33,1116.53 1765.97,1161.17 1768.67,1163.87 1768.67,1364.11 1768.67,1372.22 1641.28,1372.22 1640.43,1519.36
NetC7_1 on Top Layer "Top Layer-No Net" (solid, pour order 14): 412.28,820.55 484.32,892.59 569.63,892.59 656.56,892.59 663.71,885.43 667.94,881.21 667.94,709.08 412.99,709.08
NetD2_2 on Top Layer "Top Layer-No Net 1" (solid, pour order 22): 1213.89,891.88 1213.89,782.42 1213.89,772.89 1222.2,772.89 1452.23,772.89 1452.23,891.28
NetD3_2 on Top Layer "Top Layer-No Net 2" (solid, pour order 24): 1212.95,1093.75 1368.13,1093.75 1368.13,923.22 1212.95,923.22
NetC8_1 on Top Layer "Top Layer-No Net 3" (solid, pour order 26): 246.86,720.36 16.98,720.36 20.55,716.79 20.55,450.73 146.44,450.73 146.95,450.23 146.95,623.13 247.24,623.13
NetC3_1 on Top Layer "Top Layer-No Net 4" (solid, pour order 28): 289.01,1009.39 288.32,1008.7 288.32,905.12 314.35,880.11 314.35,850.35 333.19,850.35 345.33,850.35 345.33,862.75 391.36,908.79 392.02,909.45 392.02,958.65 341.93,958.65 337.84,962.74 327.31,973.27 327.31,1009.74
NetC1_1 on POWER "POWER-No Net" (solid, pour order 16): 0.81,1968.29 0.9,1968.2 1967.42,1968.2 1967.42,0.32 1967.36,0.38 1.56,0.38
GND on GNDS "GND1" (solid, pour order 18): 885.52,6.54 7.73,6.54 1.56,0.38 0.81,1.12 0.81,1968.29 885.52,1968.29
GND2 on GNDS "GND2" (solid, pour order 20): 916.88,0.19 1967.36,0.38 1967.36,1968.26 1963.66,1964.61 919.09,1964.61
GND on Bottom Layer "bot - gnd1" (solid, pour order 34): 3.49,1967.03 925.31,1967.03 918.24,1959.95 918.24,5.51 8.21,5.51 1.13,-1.56
GND2 on Bottom Layer "bot - gnd2" (solid, pour order 36): 1969.72,1967.03 1965.01,1971.74 927.67,1971.74 927.67,0.79 934.74,7.87 1972.08,7.87

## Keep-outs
Keep-Out Layer:
  text ".Layer_Name" at 577,-858.49 h60

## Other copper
Top Layer:
  text ".Layer_Name" at 577,-858.49 h60
Bottom Layer:
  text ".Layer_Name" at 577,-858.49 h60

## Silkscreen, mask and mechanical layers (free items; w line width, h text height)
Top Overlay:
  lines w10: 0.76,-0.43 0.76,1968.34 0.81,1968.29 1967.33,1968.29 1967.42,1968.2 1967.42,0.32 1967.36,0.38 1.56,0.38 ; 1.37,401.99 1968.53,401.99 ; 2.15,1583.98 1965.61,1583.98
  text "VOUT3" at 1654.37,1928.73 h25
  text "GND" at 1546.64,1927.55 h25
  text "GND" at 234.8,1925.94 h25
  text "VIN" at 363.98,1926.01 h25
  text "PMP20550_RevA" at 590.93,1611.16 h60
  text "30x50 mm" at 1756.82,434.07 h25
  text "50x50 mm" at 1755.09,33.73 h25
  text "GND" at 1236.85,25.56 h25
  text "GND" at 442.94,23.43 h25
  text "VOUT1" at 278.39,21.65 h25
  text "VOUT2" at 1345.21,21.76 h25
  text ".Layer_Name" at 577,-858.49 h60
Bottom Overlay:
  text ".Layer_Name" at 577,-858.49 h60
Top Paste:
  text ".Layer_Name" at 577,-858.49 h60
Bottom Paste:
  text ".Layer_Name" at 577,-858.49 h60
Top Solder:
  text ".Layer_Name" at 577,-858.49 h60
  text ".Layer_Name" at 577,-858.49 h60
Bottom Solder:
  text ".Layer_Name" at 577,-858.49 h60
Drill Guide:
  text ".Layer_Name" at 577,-858.49 h60
M1 Board Outline:
  text ".Layer_Name" at 577,-858.49 h60
M2 Board Dimensions:
  rectangle: 125,-400 500,-275
  rectangle: 0,-275 125,-150
  lines w7: 0,-275 1000,-275 ; 125,-400 125,-150 ; 250,-400 250,-150 ; 500,-400 500,-150 ; 750,-400 750,-150 ; 0,-400 0,-150 1000,-150 1000,-400 0,-400
  text ".Layer_Name" at 577,-858.49 h60
M3 3D STEP Top:
  text ".Layer_Name" at 577,-858.49 h60
M4 3D STEP Bottom:
  text ".Layer_Name" at 577,-858.49 h60
M5 Assembly Top:
  lines w10: -292,-930.17 6308,-930.17 ; -292,-726.83 6310,-726.83 ; -292,-523.5 -292,-1133.5 3713,-1133.5 6310,-1133.5 6310,-523.5 -291.5,-523.5 -291.5,-1133.5 1284,-1133.5 ; 2173,-1133.5 2173,-523.5 ; 3440,-726.83 3440,-523.5 ; 4280,-726.83 4280,-523.5 ; 4902,-1140 4902,-937.17
  text "COMPONENTS MARKED 'DNP' SHOULD NOT BE POPULATED." at 1153.5,-318.5 h60
  text "ASSEMBLY VARIANT:" at 1153,-434 h60
  text ".VariantName" at 2189,-434 h60
  text "PCB VIEWED FROM TOP SIDE" at -228.5,-655.67 h60
  text "BOARD #:" at 2248,-655.67 h60
  text ".PRJ_Number" at 2793.5,-655.67 h60
  text "REV:" at 3638,-655.67 h60
  text ".PCB_Rev" at 3929.5,-655.67 h60
  text "SVN REV:" at 4476,-655.67 h60
  text ".VersionControl_RevNumber" at 4982,-655.67 h60
  text "TID #:" at 2248,-859 h60
  text ".TID" at 2793.5,-859 h60
  text "PLOT NAME =" at -228.5,-1064.34 h60
  text ".plot_File_Name" at 577,-1064.34 h60
  text "GENERATED    :" at 2250,-1064.34 h60
  text ".Print_Date" at 3119.5,-1064.34 h60
  text ".Print_Time" at 3848.5,-1064.34 h60
  text "TEXAS INSTRUMENTS" at 5113,-1064.34 h60
M6 Assembly Bottom:
  lines w10: -292.5,-727.33 6309.5,-727.33 ; -290.5,-930.67 6309.5,-930.67 ; 1115.5,-1140.5 1115.5,-937.67 ; 1737.5,-727.33 1737.5,-524 ; 2577.5,-727.33 2577.5,-524 ; 3844.5,-1134 3844.5,-524 ; 4733.5,-1134 6309,-1134 6309,-524 -292.5,-524 -292.5,-1134 2304.5,-1134 6309.5,-1134 6309.5,-524
  text "COMPONENTS MARKED 'DNP' SHOULD NOT BE POPULATED." at 6102,-318 h60
  text ".VariantName" at 5058,-434 h60
  text "ASSEMBLY VARIANT:" at 6097,-434 h60
  text ".VersionControl_RevNumber" at 1035.5,-656.17 h60
  text "SVN REV:" at 1541.5,-656.17 h60
  text ".PCB_Rev" at 2088,-656.17 h60
  text "REV:" at 2379.5,-656.17 h60
  text ".PRJ_Number" at 3224,-656.17 h60
  text "BOARD #:" at 3769.5,-656.17 h60
  text "PCB VIEWED FROM BOTTOM SIDE" at 6246,-656.17 h60
  text ".TID" at 3224,-859.5 h60
  text "TID #:" at 3769.5,-859.5 h60
  text "TEXAS INSTRUMENTS" at 904.5,-1064.84 h60
  text ".Print_Time" at 2169,-1064.84 h60
  text ".Print_Date" at 2898,-1064.84 h60
  text "GENERATED    :" at 3767.5,-1064.84 h60
  text ".plot_File_Name" at 5440.5,-1064.84 h60
  text "PLOT NAME =" at 6246,-1064.84 h60
M9 Title Sheet:
  drawing of 57 lines, arcs and shapes, not listed
  text "1" at 739.84,8036.5 h70
  text "2" at 3235.5,8036.5 h70
  text "3" at 5724.84,8036.5 h70
  text "4" at 8231.51,8036.5 h70
  text "5" at 10730.5,8036.5 h70
  text "6" at 13235.5,8036.5 h70
  text "A" at -416.5,6893.5 h70
  text "A" at 14383.5,6893.5 h70
  text "B" at -416.5,4513.5 h70
  text "B" at 14383.5,4513.5 h70
  text "C" at -416.5,2138.5 h70
  text "C" at 14383.5,2138.5 h70
  text "PROJECT TITLE:" at 11343.5,277.5 h45
  text ".PRJ_Title" at 11393.5,144.17 h70
  text "DESIGNED FOR:" at 11343.5,-23.5 h45
  text ".PRJ_Customer" at 11393.5,-163.5 h70
  text "D" at -416.5,-231.5 h70
  text "D" at 14383.5,-231.5 h70
  text "FILE NAME:" at 11343.5,-323.5 h45
  text ".PCB_File_Name_No_Path" at 11393.5,-443.5 h70
  text "Texas Instruments (TI) and/or its licensors do not warrant the accuracy or completeness of this specification" at 6374,-605.34 h45
  text "ENGINEER:" at 11343.5,-613.5 h45
  text "LAYOUT BY:" at 12848.5,-613.5 h45
  text "or any information contained therein. TI and/or its licensors do not warrant that this design will meet" at 6329.01,-718 h45
  text ".PRJ_Engineer" at 11393.5,-768.49 h70
  text ".PCB_Layout" at 12899,-768.49 h70
  text "the specifications, will be suitable for your application or fit for any particular purpose, or will operate in" at 6329.01,-830.67 h45
  text ".Layer_Name" at 577,-858.49 h60
  text "ALTIUM DESIGNER VERSION:" at 12848.5,-923.5 h45
  text "an implementation. TI and/or its licensors do not warrant that the design is production worthy. You should" at 6329.01,-943.33 h45
  text "completely validate and test your design implementation to confirm the system functionality for your application." at 6374,-1056 h45
  text ".print_Scale" at 11393.5,-1056.83 h70
  text ".Application_BuildNumber" at 12899,-1056.83 h70
  text "1" at 739.84,-1263.5 h70
  text "2" at 3235.5,-1263.5 h70
  text "3" at 5724.84,-1263.5 h70
  text "4" at 8231.51,-1263.5 h70
  text "5" at 10730.5,-1263.5 h70
  text "6" at 13235.5,-1263.5 h70
M10 Fab Notes:
  drawing of 173 lines, arcs and shapes, not listed
  text "DESIGN INFORMATION" at 12378.02,6201 h60
  text "MIN. TRACK WIDTH:" at 11733.46,6021 h60
  text "8" at 12829.7,6021 h60
  text "MIL" at 12984.46,6021 h60
  text "MIN. CLEARANCE:" at 11733.46,5889 h60
  text "0.2" at 12769.7,5889 h60
  text "mm" at 12984.46,5889 h60
  text "MIN. VIA PAD SIZE:" at 11733.46,5757 h60
  text "24" at 12799.71,5757 h60
  text "MIL" at 12984.46,5757 h60
  text "0.05mm (2MIL)" at 12428.46,5615.29 h60
  text "MINIMUM ANNULAR RING" at 11404.23,5611 h60
  text "EXTERNAL" at 13136.46,5611 h60
  text "PER" at 11604.23,5493 h60
  text "IPC-D-275 CLASS 2 LEVEL C" at 11824.23,5493 h60
  text "MIL, HOLES" at 13312.46,5380.71 h60
  text "+/-" at 12920,5380 h60
  text "+/-" at 13774,5380 h60
  text "REGISTRATION TOLERANCES:" at 11404.23,5375 h60
  text "METAL" at 12604,5375 h60
  text "5" at 13180.2,5375 h60
  text "3" at 14013.2,5375 h60
  text "MIL" at 14129.46,5375 h60
  text "+/-" at 13774,5262 h60
  text "HOLE SIZE TOLERANCE (UNLESS OTHERWISE SPECIFIED):" at 11404.23,5257 h60
  text "3" at 14013.2,5257 h60
  text "MIL" at 14129.46,5257 h60
  text "MATERIAL:" at 11329.46,5047.54 h60
  text "FR-4 High Tg" at 12315.9,4907.21 h60
  text "FR-408" at 11750.46,4898.64 h60
  text "OTHER" at 13238.46,4898.64 h60
  text "X" at 12161,4895 h60
  text "62 MIL (1.6mm) +/-10%" at 12070.56,4735.92 h60
  text "THICKNESS:" at 11404.23,4731.64 h60
  text "X" at 11942.4,4731.64 h60
  text "OTHER" at 13355.46,4731.64 h60
  text "TOLERANCE:" at 11404.23,4573.64 h60
  text "X" at 12243.53,4573.64 h60
  text "ANSI IPC-6012 TYPE 3 CLASS 2" at 12430.48,4573.64 h60
  text "OTHER +/-" at 12430.46,4417.64 h60
  text "BOW & TWIST:" at 11404.23,4260.64 h60
  text "X" at 12243.53,4260.64 h60
  text "ANSI IPC-6012 TYPE 3 CLASS 2" at 12430.48,4260.64 h60
  text "OTHER +/-" at 12430.46,4102.13 h60
  text "DRILLING:" at 11329.46,3963.64 h60
  text "REFERENCE:" at 11404.23,3846.64 h60
  text "X" at 12052.46,3846.64 h60
  text "AS SHOWN" at 12239.46,3846.64 h60
  text "X" at 12953.46,3846.64 h60
  text "NC_DRILL FILES" at 13090.46,3846.64 h60
  text "PTH COPPER THICKNESS:" at 11404.23,3688.64 h60
  text "X" at 12534.46,3688.64 h60
  text "20-30 um" at 12671.46,3688.64 h60
  text "OTHER" at 13388.46,3688.64 h60
  text "BOARD FINISH:" at 11329.46,3529.64 h60
  text "SILKSCREEN:" at 11484.68,3411.64 h60
  text "X" at 12433.46,3411.64 h60
  text "TOP" at 12559.46,3411.64 h60
  text "X" at 12943.46,3411.64 h60
  text "BOTTOM" at 13070.46,3411.64 h60
  text "SILKSCREEN COLOR:" at 11484.68,3244.64 h60
  text "X" at 12432.42,3244.64 h60
  text "WHITE" at 12559.46,3244.64 h60
  text "OTHER" at 13070.46,3244.64 h60
  text "X" at 12563.42,3085.44 h60
  text "GREEN" at 12690.46,3085.44 h60
  text "OTHER" at 13308.46,3085.44 h60
  text "SOLDER RESIST COLOR:" at 11484.68,3074.64 h60
  text "X" at 12563.42,2915.44 h60
  text "MATTE" at 12690.46,2915.44 h60
  text "SEMI-GLOSS" at 13308,2914.8 h60
  text "IMMERSION GOLD (ENIG)" at 12390.46,2726.92 h60
  text "ENEPIG" at 13728,2723.64 h60
  text "SURFACE FINISH:" at 11329.46,2722.64 h60
  text "X" at 12203.51,2722.64 h60
  text "IMM. TIN/SILVER OR EQUIV" at 11659,2565.64 h60
  text "OTHER" at 13090.46,2565.64 h60
  text "ARRAY/PANEL:" at 11329.46,2386.64 h60
  text "CUT AND TRIM PER M1 BOARD OUTLINE" at 12390.46,2382.35 h60
  text "N.C. ROUTE" at 12390.46,2230.64 h60
  text "X" at 13069.46,2230.64 h60
  text "V. SCORE" at 13256.46,2230.64 h60
  text "CERTIFICATION:" at 11329.46,2093.64 h60
  text "MATERIALS AND WORKMANSHIP FOR ALL PCBS" at 12054.46,2093.64 h60
  text "TO MEET OR EXCEED THE REQUIREMENTS OF:" at 12054.46,1995.64 h60
  text "X" at 11680.96,1859.13 h60
  text "ANSI IPC-A-600F CLASS ->" at 11819.96,1859.13 h60
  text "X" at 13459.02,1859.13 h60
  text "2" at 13577.96,1859.14 h60
  text "1" at 13262.96,1857.64 h60
  text "3" at 13931.96,1857.64 h60
  text "X" at 12495.02,1699.64 h60
  text "RoHS" at 12631.96,1699.64 h60
  text "OTHER" at 13276.36,1699.64 h60
  text "PER ORDER" at 13673.42,1699.64 h60
  text "ALL BOARDS MUST MEET OR EXCEED UL94-V0 REQUIREMENTS." at 11357,1534 h60
  text "PCB MUST BEAR THE UL94V-0 UL REGISTERED MATERIAL ID NUMBER" at 11357,1414 h60
  text "ADDITIONAL REQUIREMENTS:" at 11329.46,1240.64 h60
  text "MICROSECTION:" at 11404.23,1125.64 h60
  text "YES" at 12309.96,1125.64 h60
  text "REQUIRED" at 13171.46,969.49 h60
  text "BARE BOARD ELEC. TEST:" at 11404.23,966.64 h60
  text "NONE" at 12709.96,966.64 h60
  text "X" at 13044.46,966.64 h60
  text "PER ORDER" at 13763.46,966.64 h60
  text ".Layer_Name" at 577,-858.49 h60
M11 Gerber Information:
  lines w10: -292,-930.17 6308,-930.17 ; -292,-726.83 6310,-726.83 ; -292,-523.5 -292,-1133.5 3713,-1133.5 6310,-1133.5 6310,-523.5 -291.5,-523.5 -291.5,-1133.5 1284,-1133.5 ; 2173,-1133.5 2173,-523.5 ; 3440,-726.83 3440,-523.5 ; 4280,-726.83 4280,-523.5 ; 4902,-1140 4902,-937.17
  text "ALL ARTWORK VIEWED FROM TOP SIDE" at -228.5,-655.67 h60
  text "BOARD #:" at 2248,-655.67 h60
  text ".PRJ_Number" at 2793.5,-655.67 h60
  text "REV:" at 3638,-655.67 h60
  text ".PCB_Rev" at 3929.5,-655.67 h60
  text "SVN REV:" at 4476,-655.67 h60
  text ".VersionControl_RevNumber" at 4982,-655.67 h60
  text "LAYER NAME =" at -228.5,-858.49 h60
  text "TID #:" at 2248,-859 h60
  text ".TID" at 2793.5,-859 h60
  text "PLOT NAME =" at -228.5,-1064.34 h60
  text ".plot_File_Name" at 577,-1064.34 h60
  text "GENERATED    :" at 2250,-1064.34 h60
  text ".Print_Date" at 3119.5,-1064.34 h60
  text ".Print_Time" at 3848.5,-1064.34 h60
  text "TEXAS INSTRUMENTS" at 5113,-1064.34 h60
M12 Stackup:
  text ".Layer_Name" at 577,-858.49 h60
M13 Component Bodies Top:
  text ".Layer_Name" at 577,-858.49 h60
M14 Component Bodies Bottom:
  text ".Layer_Name" at 577,-858.49 h60
M15 Courtyards Top:
  text ".Layer_Name" at 577,-858.49 h60
M16 Courtyards Bottom:
  text ".Layer_Name" at 577,-858.49 h60
Drill Drawing:
  text ".Layer_Name" at 577,-858.49 h60
M17 Embedded Cavity:
  text ".Layer_Name" at 577,-858.49 h60
M18 Embedded Assembly:
  text ".Layer_Name" at 577,-858.49 h60
M19 Embedded Keepout:
  text ".Layer_Name" at 577,-858.49 h60

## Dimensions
0,-400 to 1000,-400 on M2 Board Dimensions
